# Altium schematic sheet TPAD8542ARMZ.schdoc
size 127 x 101 mm
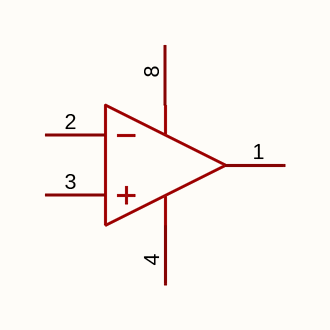
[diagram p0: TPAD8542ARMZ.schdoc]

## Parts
U?  tpad8542armz  [MSOP-8_L3.0-W3.0-P0.65-LS4.9-BL-1]  (value not drawn)  (part A of 2)

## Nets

Not connected (* = marked no-connect by the designer): U? 1(OUT1) 2(IN1-) 3(IN1+) 4(VEE) 8(VCC)

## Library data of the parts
U? = tpad8542armz: 放大器数:2;轨到轨:轨到轨输入,轨到轨输出;增益带宽积(GBW):1MHz;输入失调电压(Vos):5mV;压摆率(SR):-;输入偏置电流(Ib):10pA;; Manufacturer: TECH PUBLIC(台舟); AddInBom: yes; ModelId: 374647af99ae41c4bb682bd336d5e4ed; ModelTransform: 118.11,192.913,0,0,0,0,0,0,0; Number of Channels: 2; Maximum Power Supply Range (Vdd-Vss): 5.5V; Gain Bandwidth Product: 1MHz; Vos - Input Offset Voltage: 5mV; Input Offset Voltage Drift(Vos TC): 650nV/℃; Ib - Input Bias Current: 10pA; Common Mode Rejection Ratio(CMRR): 85dB; Quiescent Current: 40uA; Output Current: 20mA; Single supply: 2.2V~5.5V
